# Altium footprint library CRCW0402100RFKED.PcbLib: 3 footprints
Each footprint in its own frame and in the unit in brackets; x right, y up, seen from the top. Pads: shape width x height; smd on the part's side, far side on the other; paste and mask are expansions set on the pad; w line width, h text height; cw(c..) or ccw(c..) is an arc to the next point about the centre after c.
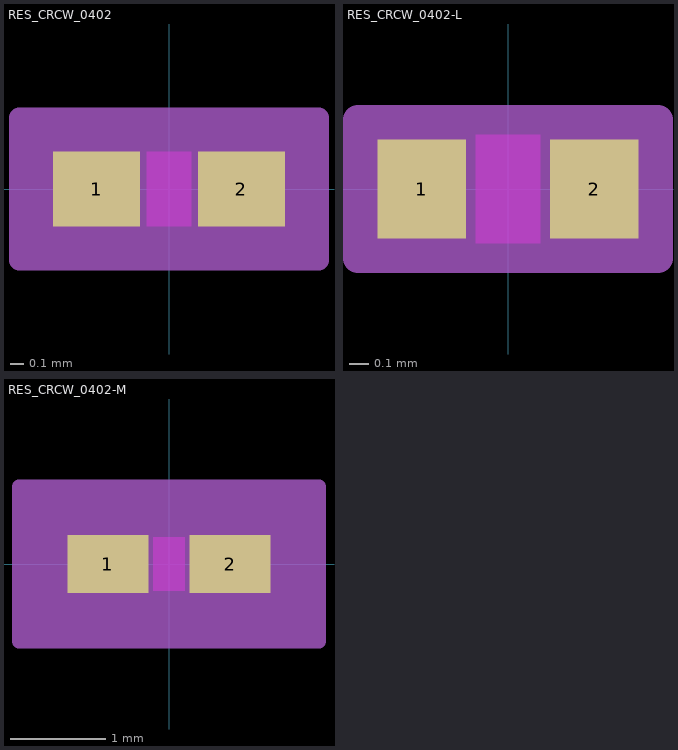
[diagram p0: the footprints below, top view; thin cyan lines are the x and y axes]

## RES_CRCW_0402 [mil]
pads (2):
  rect 25.78x22 smd paste+0 mask+0: 1(-21.39,0) 2(21.39,0)
Top Layer keep-out:
  region: -6.5,-9 -6.5,9 6.5,9 6.5,-9
Top Overlay:
  text ".Designator" at -137.5,-25 h50
Keep-Out Layer:
  region: -6.5,-11 -6.5,11 6.5,11 6.5,-11
Mechanical 13:
  lines w1: -20.5,-11 -20.5,11 ; -20.5,-11 -8.5,-11 -8.5,11 -20.5,11 ; -20.5,-11 20.5,-11 ; -20.5,-11 -20.5,11 ; -20.5,11 20.5,11 ; 20.5,-11 8.5,-11 8.5,11 20.5,11 ; 20.5,-11 20.5,11 ; 20.5,-11 20.5,11
  text ".Designator" at -137.5,-25 h50
Mechanical 15:
  region: 44.28,-21 -44.28,-21 -44.28,21 44.28,21
  lines w6: -44.28,-21 -44.28,21 44.28,21 44.28,-21 -44.28,-21
3D body "RES_CRCW_0402.step": height 15.98, standoff 0, extent -20.51,-10.98 20.51,10.98

## RES_CRCW_0402-L [mil]
pads (2):
  rect 17.91x20.03 smd paste+0 mask+0: 1(-17.45,0) 2(17.45,0)
Top Layer keep-out:
  region: -6.5,-9 -6.5,9 6.5,9 6.5,-9
Top Overlay:
  text ".Designator" at -137.5,-25 h50
Keep-Out Layer:
  region: -6.5,-11 -6.5,11 6.5,11 6.5,-11
Mechanical 13:
  lines w1: -20.5,-11 -20.5,11 ; -20.5,-11 -8.5,-11 -8.5,11 -20.5,11 ; -20.5,-11 20.5,-11 ; -20.5,-11 -20.5,11 ; -20.5,11 20.5,11 ; 20.5,-11 8.5,-11 8.5,11 20.5,11 ; 20.5,-11 20.5,11 ; 20.5,-11 20.5,11
  text ".Designator" at -137.5,-25 h50
Mechanical 15:
  region: 30.41,-14.02 -30.41,-14.02 -30.41,14.02 30.41,14.02
  lines w6: -30.41,-14.02 -30.41,14.02 30.41,14.02 30.41,-14.02 -30.41,-14.02
3D body "RES_CRCW_0402.step": height 15.98, standoff 0, extent -20.51,-10.98 20.51,10.98

## RES_CRCW_0402-M [mil]
pads (2):
  rect 33.65x23.97 smd paste+0 mask+0: 1(-25.33,0) 2(25.33,0)
Top Layer keep-out:
  region: -6.5,-9 -6.5,9 6.5,9 6.5,-9
Top Overlay:
  text ".Designator" at -137.5,-25 h50
Keep-Out Layer:
  region: -6.5,-11 -6.5,11 6.5,11 6.5,-11
Mechanical 13:
  lines w1: -20.5,-11 -20.5,11 ; -20.5,-11 -8.5,-11 -8.5,11 -20.5,11 ; -20.5,-11 20.5,-11 ; -20.5,-11 -20.5,11 ; -20.5,11 20.5,11 ; 20.5,-11 8.5,-11 8.5,11 20.5,11 ; 20.5,-11 20.5,11 ; 20.5,-11 20.5,11
  text ".Designator" at -137.5,-25 h50
Mechanical 15:
  region: 62.15,-31.98 -62.15,-31.98 -62.15,31.98 62.15,31.98
  lines w6: -62.15,-31.98 -62.15,31.98 62.15,31.98 62.15,-31.98 -62.15,-31.98
3D body "RES_CRCW_0402.step": height 15.98, standoff 0, extent -20.51,-10.98 20.51,10.98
